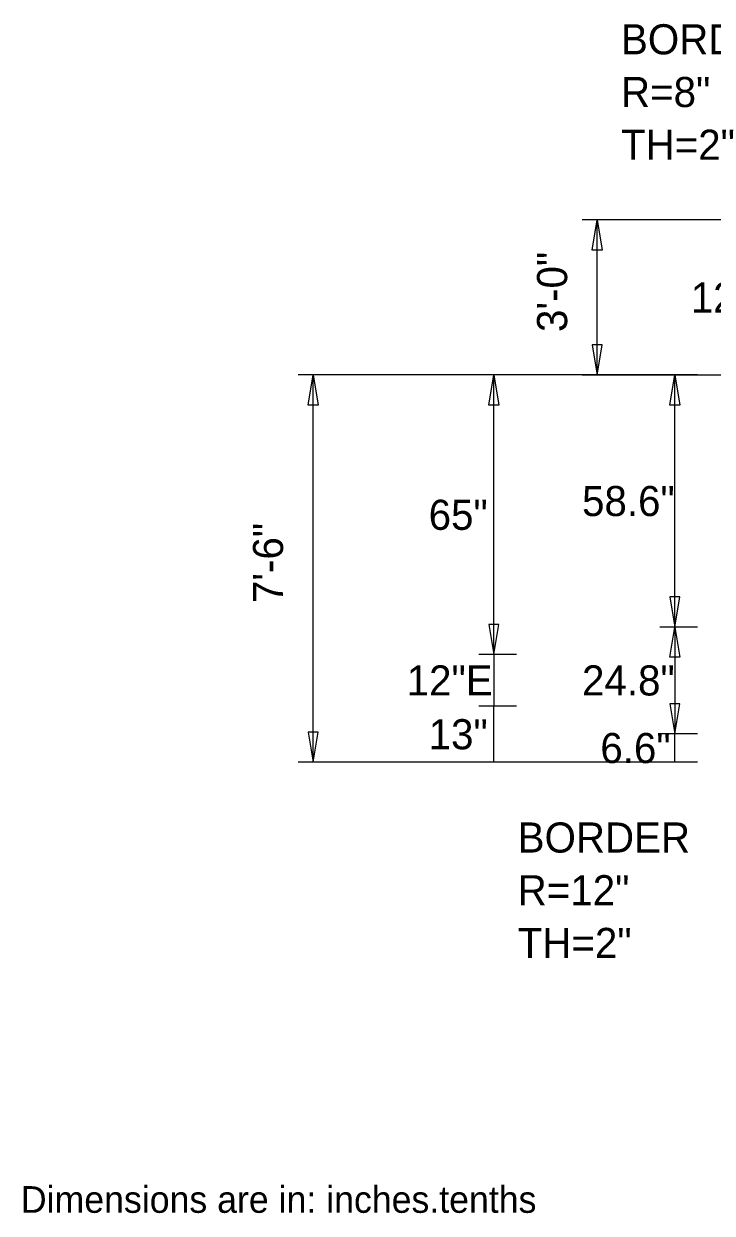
# Model space of a CAD drawing. Extents: x 2149934 to 2150188, y 145114 to 145238.
# Drawn here: x 2149947.92 to 2149961.24, y 145187.96 to 145211 of the extents above; entities that cross this region are included whole.
import ezdxf

# ---------------------------------------------------------------- set-up
doc = ezdxf.new("R2010")
doc.units = 0
doc.layers.add('GSDIMS', color=7, linetype='Continuous')
doc.layers.add('Level 1', color=7, linetype='Continuous')

msp = doc.modelspace()

# ---------------------------------------------------------------- linework, layer by layer
at = {"layer": 'GSDIMS'}
for p, q in [((2149959.458, 145207.196), (2149958.728, 145207.196)), ((2149959.02, 145204.194), (2149959.02, 145207.196)), ((2149962.958, 145207.196), (2149959.458, 145207.196)), ((2149953.958, 145204.195), (2149953.229, 145204.195)), ((2149953.52, 145196.695), (2149953.52, 145204.195)), ((2149960.958, 145204.195), (2149953.958, 145204.195)), ((2149957.458, 145204.195), (2149956.729, 145204.195)), ((2149957.02, 145198.778), (2149957.02, 145204.195)), ((2149959.458, 145204.194), (2149958.728, 145204.194)), ((2149962.958, 145204.194), (2149959.458, 145204.194)), ((2149960.958, 145204.195), (2149960.229, 145204.195)), ((2149960.52, 145199.312), (2149960.52, 145204.195)), ((2149960.958, 145199.312), (2149960.229, 145199.312)), ((2149960.958, 145199.312), (2149960.229, 145199.312)), ((2149960.52, 145199.312), (2149960.52, 145197.245)), ((2149957.458, 145198.778), (2149956.729, 145198.778)), ((2149957.458, 145198.778), (2149956.729, 145198.778)), ((2149957.02, 145198.778), (2149957.02, 145197.778)), ((2149957.458, 145197.778), (2149956.729, 145197.778)), ((2149957.458, 145197.778), (2149956.729, 145197.778)), ((2149957.02, 145196.695), (2149957.02, 145197.778)), ((2149960.958, 145197.245), (2149960.229, 145197.245)), ((2149960.958, 145197.245), (2149960.229, 145197.245)), ((2149960.52, 145196.695), (2149960.52, 145197.245)), ((2149953.958, 145196.695), (2149953.229, 145196.695)), ((2149960.958, 145196.695), (2149953.958, 145196.695)), ((2149957.458, 145196.695), (2149956.729, 145196.695)), ((2149960.958, 145196.695), (2149960.229, 145196.695))]:
    msp.add_line(p, q, dxfattribs=at)
for points in [[(2149959.02, 145207.196), (2149959.117, 145206.612), (2149958.923, 145206.612)], [(2149959.02, 145204.194), (2149959.117, 145204.778), (2149958.923, 145204.778)], [(2149953.52, 145204.195), (2149953.617, 145203.611), (2149953.423, 145203.611)], [(2149957.02, 145204.195), (2149957.117, 145203.611), (2149956.923, 145203.611)], [(2149960.52, 145204.195), (2149960.617, 145203.611), (2149960.423, 145203.611)], [(2149960.52, 145199.312), (2149960.617, 145199.895), (2149960.423, 145199.895)], [(2149957.02, 145198.778), (2149957.117, 145199.362), (2149956.923, 145199.362)], [(2149960.52, 145199.312), (2149960.617, 145198.728), (2149960.423, 145198.728)], [(2149960.52, 145197.245), (2149960.617, 145197.828), (2149960.423, 145197.828)], [(2149953.52, 145196.695), (2149953.617, 145197.278), (2149953.423, 145197.278)]]:
    msp.add_lwpolyline(points, close=True, dxfattribs=at)

# ---------------------------------------------------------------- texts
for s, p in [('BORDER', (2149959.479, 145210.404)), ('R=8"', (2149959.479, 145209.383)), ('TH=2"', (2149959.479, 145208.362)), ('12"E', (2149960.83, 145205.403)), ('58.6"', (2149958.725, 145201.462)), ('65"', (2149955.755, 145201.195)), ('12"E', (2149955.33, 145197.987)), ('24.8"', (2149958.725, 145197.987)), ('13"', (2149955.755, 145196.945)), ('6.6"', (2149959.079, 145196.678)), ('BORDER', (2149957.479, 145194.945)), ('R=12"', (2149957.479, 145193.924)), ('TH=2"', (2149957.479, 145192.903))]:
    msp.add_text(s, height=0.5833, dxfattribs=at).set_placement(p)
for s, p in [('3\'-0"', (2149958.437, 145205.027)), ('7\'-6"', (2149952.937, 145199.777))]:
    msp.add_text(s, height=0.5833, rotation=90, dxfattribs=at).set_placement(p)
at = {"layer": 'Level 1'}
msp.add_text('Dimensions are in: inches.tenths', height=0.51652, dxfattribs=at).set_placement((2149947.86, 145187.968))

doc.saveas('drawing.dxf')
